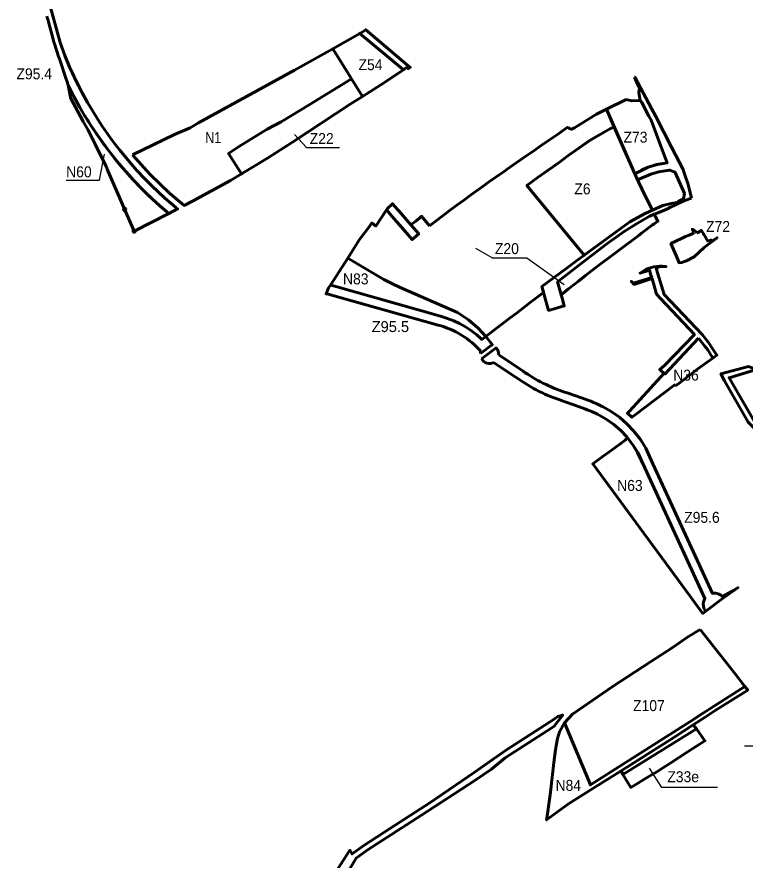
# Model space of a CAD drawing. Extents: x -650277 to -643420, y -1073980 to -1066720.
# Drawn here: x -649120 to -647523, y -1072548 to -1070698 of the extents above; entities that cross this region are included whole.
import ezdxf

# ---------------------------------------------------------------- set-up
doc = ezdxf.new("R2010")
doc.units = 0
doc.header["$LTSCALE"] = 9.6
doc.header["$PDMODE"] = 32
doc.header["$PDSIZE"] = 4.8
for name, color, linetype, lineweight in [('1', 7, 'Continuous', 60), ('15', 7, 'Continuous', 60), ('18', 7, 'Continuous', 60), ('34', 7, 'Continuous', 60), ('42', 7, 'Continuous', 60), ('45', 7, 'Continuous', 60), ('60', 7, 'Continuous', 60), ('63', 7, 'Continuous', 25), ('7', 7, 'Continuous', 60), ('8', 7, 'Continuous', 60), ('9', 7, 'Continuous', 60)]:
    doc.layers.add(name, color=color, linetype=linetype, lineweight=lineweight)

msp = doc.modelspace()

# ---------------------------------------------------------------- linework, layer by layer
at = {"layer": '1'}
for points in [[(-648540.7, -1070928.6), (-648571.14, -1070944.67), (-648634.07, -1070983.17), (-648655.76, -1070997.5), (-648627.39, -1071042.65), (-648605.3, -1071029.34), (-648570.23, -1071008.2), (-648515.46, -1070972.94), (-648389.33, -1070889.79), (-648362.519, -1070872.788), (-648386.587, -1070833.807), (-648479.18, -1070891.26)], [(-648215.08, -1071156.35), (-648232.8, -1071135.6), (-648237.46, -1071139.38), (-648245.49, -1071145.91), (-648256.04, -1071154.5), (-648238.84, -1071174.33), (-648253.126, -1071186.542), (-648292.587, -1071141.054), (-648309.41, -1071121.655), (-648333.002, -1071157.07), (-648341.943, -1071150.071), (-648347.949, -1071158.385), (-648368.48, -1071186.81), (-648394.104, -1071227.17), (-648315.127, -1071274.052), (-648292.406, -1071286.112), (-648274.918, -1071293.751), (-648154.21, -1071346.477), (-648130, -1071363), (-648109, -1071381), (-648091.92, -1071399.07), (-648060.01, -1071374.69), (-648038.18, -1071358.51), (-648025.39, -1071348.76), (-647994.31, -1071325.03), (-647965.26, -1071302.86), (-647966.226, -1071299.385), (-647968.896, -1071289.779), (-647916.208, -1071250.662), (-647895.959, -1071235.746), (-647875.939, -1071221.104), (-648001.922, -1071067.83), (-647977.41, -1071049.74), (-647930.96, -1071017.383), (-647912.11, -1071003.11), (-647864.29, -1070969.503), (-647818.33, -1070942.91), (-647810.243, -1070939.825), (-647827.527, -1070900.351), (-647848.89, -1070911.21), (-647897.76, -1070941.62), (-647904.13, -1070944.78), (-647909.42, -1070942.63), (-647908.63, -1070942.1), (-647913.45, -1070940.79), (-647934.9, -1070955.87), (-647952.01, -1070967.82), (-647970.19, -1070980.45), (-647988.81, -1070993.27), (-648008.34, -1071006.32), (-648030.24, -1071021.91), (-648044.82, -1071032.25), (-648051.48, -1071036.97), (-648062.53, -1071044.59), (-648085.73, -1071060.92), (-648097.61, -1071069.37), (-648102.55, -1071072.86), (-648125.53, -1071089.51), (-648141.12, -1071100.71), (-648155.77, -1071111.23), (-648172.48, -1071123.95), (-648197.57, -1071143.03)], [(-648001.922, -1071067.83), (-647977.41, -1071049.74), (-647930.7, -1071017.18), (-647911.838, -1071002.919), (-647864.03, -1070969.3), (-647864.03, -1070969.3), (-647818.33, -1070942.91), (-647810.243, -1070939.825), (-647759.52, -1071055.67), (-647757.19, -1071059.66), (-647742.64, -1071090.72), (-647726.74, -1071122.48), (-647742.35, -1071129.43), (-647775.982, -1071148.001), (-647775.982, -1071148.001), (-647875.939, -1071221.104)], [(-647756.03, -1071176.76), (-647750.34, -1071172.5), (-647726.56, -1071154.68), (-647723.79, -1071152.61), (-647720.85, -1071150.41), (-647714.71, -1071146.51), (-647719.73, -1071136.48), (-647722.51, -1071130.93), (-647732.58, -1071135.04), (-647733.38, -1071135.37), (-647737.027, -1071137.593), (-647761.366, -1071152.304), (-647788.66, -1071168.8), (-647826.56, -1071195.86), (-647889.22, -1071244.48), (-647915.6, -1071264.95), (-647934.6, -1071279.45), (-647926.69, -1071307.81), (-647910.73, -1071295.08), (-647907.92, -1071292.84), (-647888.77, -1071277.56), (-647873.25, -1071265.17), (-647850.956, -1071248.208)]]:
    msp.add_lwpolyline(points, close=True, dxfattribs=at)
at = {"layer": '15'}
msp.add_line((-648272.453, -1070814.072), (-648271.1, -1070813.17), dxfattribs=at)
for points in [[(-648271.1, -1070813.17), (-648267.8, -1070810.96), (-648264.38, -1070808.66), (-648262.15, -1070811.96), (-648257.61, -1070808.91), (-648355.275, -1070726.455), (-648360.83, -1070729.87), (-648366.739, -1070733.501), (-648368.163, -1070734.376), (-648272.453, -1070814.072)], [(-647659.01, -1071032.66), (-647685.1, -1070983.93), (-647719.06, -1070916.45), (-647728.35, -1070899.11), (-647764.84, -1070830.47), (-647765.72, -1070830.64)], [(-647765.72, -1070830.64), (-647759.08, -1070845.74), (-647755.87, -1070853.02), (-647754.6, -1070856.11), (-647756.45, -1070863.95), (-647753.81, -1070881.3)], [(-647753.81, -1070881.3), (-647749.75, -1070886.1), (-647734.48, -1070915.94), (-647729.27, -1070924.35), (-647701.45, -1070999.4)], [(-647701.45, -1070999.4), (-647694.54, -1071018.549), (-647718, -1071022), (-647736, -1071028), (-647750, -1071034), (-647765.408, -1071042.223), (-647759.52, -1071055.67), (-647730.17, -1071043.21), (-647712.74, -1071037.99), (-647688.9, -1071034.18), (-647676.96, -1071039.014)], [(-647640.727, -1071095.819), (-647648.106, -1071065.551), (-647654.747, -1071047.095), (-647657.699, -1071038.232), (-647659.01, -1071032.66)], [(-647676.96, -1071039.014), (-647676.9, -1071039.03), (-647676.45, -1071039.22), (-647656.443, -1071085.369), (-647658.55, -1071097.02), (-647669.02, -1071102.33), (-647667.35, -1071106.38), (-647655.47, -1071100.98), (-647640.727, -1071095.819)], [(-647498.271, -1071593.544), (-647558.654, -1071489.738), (-647498.8, -1071471.94), (-647515.87, -1071465.25), (-647576.471, -1071481.091), (-647568.35, -1071496.656), (-647516.376, -1071586.89), (-647490.561, -1071613.609)]]:
    msp.add_lwpolyline(points, dxfattribs=at)
for points in [[(-647734.48, -1070915.94), (-647741.21, -1070902.78), (-647749.75, -1070886.1)], [(-648238.84, -1071174.33), (-648256.04, -1071154.5), (-648278.39, -1071128.74), (-648296.34, -1071108.04), (-648307.33, -1071118.47), (-648309.41, -1071121.655), (-648292.587, -1071141.054), (-648270.236, -1071166.815), (-648253.126, -1071186.542)], [(-647826.56, -1071195.86), (-647788.66, -1071168.8), (-647761.366, -1071152.304), (-647737.027, -1071137.593), (-647733.38, -1071135.37), (-647732.58, -1071135.04), (-647722.51, -1071130.93), (-647716.51, -1071128.48), (-647695.08, -1071119.72), (-647685.55, -1071115.14), (-647684.15, -1071114.47), (-647680.64, -1071112.77), (-647667.35, -1071106.38), (-647669.02, -1071102.33), (-647674.17, -1071104.97), (-647675.64, -1071105.71), (-647680.82, -1071106.54), (-647688.45, -1071108.38), (-647701.04, -1071111.41), (-647703.96, -1071112.11), (-647726.74, -1071122.48), (-647742.35, -1071129.43), (-647775.982, -1071148.001), (-647895.959, -1071235.746), (-647916.161, -1071250.628), (-647916.208, -1071250.662), (-647968.896, -1071289.779), (-647965.26, -1071302.86), (-647954.38, -1071342), (-647934.51, -1071336.37), (-647919.88, -1071332.23), (-647924.53, -1071315.55), (-647934.6, -1071279.45), (-647915.6, -1071264.95), (-647889.22, -1071244.48)], [(-647625.428, -1071403.267), (-647612.269, -1071419.742), (-647605.292, -1071428.816), (-647594.43, -1071446.543), (-647585.273, -1071440.044), (-647595.335, -1071424.564), (-647603.9, -1071412.1), (-647617.49, -1071394.901), (-647700.816, -1071307.512), (-647715.355, -1071259.885), (-647718.342, -1071248.972), (-647711.447, -1071246.332), (-647696.81, -1071245.79), (-647705.59, -1071245.08), (-647710.94, -1071244.65), (-647723.57, -1071246.66), (-647738.56, -1071251.13), (-647753.647, -1071260.178), (-647733.15, -1071254.081), (-647729.795, -1071265.066), (-647728.006, -1071269.975), (-647768.445, -1071282.6), (-647772.97, -1071278.43), (-647772.07, -1071279.33), (-647766.35, -1071285.11), (-647727.368, -1071272.362), (-647717.363, -1071306.29), (-647708.429, -1071316.821), (-647634.524, -1071394.901), (-647700.078, -1071462.96), (-647710.546, -1071472.023), (-647699.767, -1071481.617)], [(-647795.4, -1072352.415), (-647679.66, -1072279.15), (-647637.082, -1072251.377), (-647629.67, -1072259.82), (-647791.198, -1072360.119)]]:
    msp.add_lwpolyline(points, close=True, dxfattribs=at)
at = {"layer": '18'}
for points in [[(-647783.95, -1070879.58), (-647827.363, -1070900.725), (-647765.408, -1071042.223), (-647736, -1071028), (-647715.488, -1071021.631)], [(-647783.95, -1070879.58), (-647827.363, -1070900.725), (-647765.408, -1071042.223), (-647736, -1071028), (-647715.488, -1071021.631)], [(-647715.488, -1071021.631), (-647694.54, -1071018.549), (-647701.45, -1070999.4), (-647729.27, -1070924.35), (-647734.48, -1070915.94), (-647749.75, -1070886.1), (-647753.81, -1070881.3), (-647771.47, -1070882.27), (-647783.95, -1070879.58)], [(-647715.488, -1071021.631), (-647694.54, -1071018.549), (-647701.45, -1070999.4), (-647729.27, -1070924.35), (-647734.48, -1070915.94), (-647749.75, -1070886.1), (-647753.81, -1070881.3), (-647771.47, -1070882.27), (-647783.95, -1070879.58)]]:
    msp.add_lwpolyline(points, dxfattribs=at)
at = {"layer": '34'}
for points in [[(-647621.97, -1072041.73), (-647649.76, -1072059.06), (-647683.63, -1072081.94), (-647730.53, -1072112.84), (-647814.58, -1072167.67), (-647845.58, -1072188.94), (-647901.91, -1072227.6), (-647919.68, -1072247.09), (-647862.615, -1072383.084)], [(-647523.71, -1072167.071), (-647545.44, -1072139.35), (-647621.97, -1072041.73)], [(-647862.615, -1072383.084), (-647800.2, -1072343.615), (-647642.504, -1072242.974), (-647616.719, -1072226.154), (-647523.71, -1072167.071)]]:
    msp.add_lwpolyline(points, dxfattribs=at)
at = {"layer": '42'}
for p, q in [((-648883.73, -1071120.13), (-648862.97, -1071168.09)), ((-648862.97, -1071168.09), (-648787.207, -1071129.363))]:
    msp.add_line(p, q, dxfattribs=at)
for points in [[(-649002.97, -1070857.609), (-649007.885, -1070848.153), (-649003.1, -1070871.35), (-649002.82, -1070872.69), (-649002.62, -1070873.69), (-649002.15, -1070875.96), (-648974.4, -1070927.77), (-648963.5, -1070946.45), (-648959.92, -1070953.73), (-648948.29, -1070977.37), (-648924.92, -1071024.89), (-648922.98, -1071029.49), (-648921.87, -1071032.04), (-648892.82, -1071099.15), (-648883.73, -1071120.13)], [(-648994.42, -1070874.053), (-648994.464, -1070873.974), (-648994.52, -1070873.867)], [(-648982.403, -1070895.812), (-648982.467, -1070895.704), (-648982.524, -1070895.601)], [(-648970.64, -1070915.778), (-648970.712, -1070915.663), (-648970.771, -1070915.564)], [(-648960.194, -1070932.542), (-648960.268, -1070932.429), (-648960.34, -1070932.313)], [(-648949.345, -1070949.096), (-648949.389, -1070949.031), (-648949.428, -1070948.972)], [(-648939.179, -1070963.89), (-648939.232, -1070963.818), (-648939.33, -1070963.675)], [(-648918.464, -1070992.141), (-648918.601, -1070991.969), (-648918.737, -1070991.784)], [(-648292.406, -1071286.112), (-648315.127, -1071274.052), (-648394.104, -1071227.17), (-648432.093, -1071286.645)], [(-648432.093, -1071286.645), (-648426.18, -1071288.32), (-648191.25, -1071354.858)], [(-648091.92, -1071399.07), (-648109, -1071381), (-648130, -1071363), (-648154.21, -1071346.477), (-648274.918, -1071293.751), (-648292.406, -1071286.112)], [(-648191.25, -1071354.858), (-648178.158, -1071358.781), (-648162.084, -1071364.918), (-648149.571, -1071370.788), (-648136.263, -1071378.194), (-648123.313, -1071386.696), (-648111.646, -1071395.618), (-648103.268, -1071402.88), (-648100.438, -1071405.517), (-648091.92, -1071399.07)], [(-647625.428, -1071403.267), (-647699.767, -1071481.617), (-647701.415, -1071480.15), (-647708.18, -1071487.57), (-647776.13, -1071562.1)], [(-647676.51, -1071504.34), (-647674.28, -1071506.59), (-647656.27, -1071493.04), (-647626.7, -1071470.46), (-647611.82, -1071459.38), (-647594.43, -1071446.543), (-647605.292, -1071428.816), (-647612.269, -1071419.742), (-647625.428, -1071403.267)], [(-647776.13, -1071562.1), (-647781.31, -1071567.79), (-647771.717, -1071576.551), (-647764.23, -1071571.01), (-647676.51, -1071504.34)], [(-647637.082, -1072251.377), (-647611.306, -1072234.563), (-647589.02, -1072219.66), (-647517.51, -1072174.98), (-647523.71, -1072167.071), (-647616.719, -1072226.154), (-647642.504, -1072242.974), (-647800.2, -1072343.615)], [(-647800.2, -1072343.615), (-647862.615, -1072383.084), (-647919.68, -1072247.09), (-647930.36, -1072266.38), (-647934.86, -1072280.99), (-647939.26, -1072306.1), (-647942.54, -1072333.82), (-647950.2, -1072398.61), (-647956.786, -1072446.511), (-647958.82, -1072459.74), (-647910.27, -1072424.51), (-647857.52, -1072391.14), (-647795.4, -1072352.415)], [(-647795.4, -1072352.415), (-647679.66, -1072279.15), (-647637.082, -1072251.377)]]:
    msp.add_lwpolyline(points, dxfattribs=at)
for start, end in [(206.85611, 208.07207), (208.08607, 209.71957), (209.73567, 211.25686), (211.27351, 212.56631), (212.58435, 213.8879), (213.89777, 215.07157), (215.08899, 217.38409), (217.41391, 230.04071)]:
    msp.add_arc((-648232.695, -1070467.567), 863.398, start, end, dxfattribs=at)
for p in [(-648883.73, -1071120.13), (-648862.97, -1071168.09)]:
    msp.add_point(p, dxfattribs=at)
at = {"layer": '45'}
msp.add_lwpolyline([(-647817.33, -1071649.51), (-647806.35, -1071641.47), (-647795.76, -1071633.72), (-647794.98, -1071633.15), (-647786.1, -1071626.65), (-647781.134, -1071621.645), (-647769.498, -1071636.647), (-647758.889, -1071653.742), (-647743.48, -1071687.426), (-647611.514, -1071974.086), (-647613.455, -1071978.031), (-647614.654, -1071982.238), (-647615.083, -1071986.65), (-647614.76, -1071990.762), (-647613.637, -1071995.081), (-647611.779, -1071999.069), (-647609.808, -1072001.962), (-647616.12, -1072006.7), (-647621.06, -1072000), (-647644.38, -1071968.3), (-647705.291, -1071885.501), (-647727.85, -1071854.86), (-647857.52, -1071678.92), (-647834.345, -1071661.969), (-647827.42, -1071656.89)], close=True, dxfattribs=at)
at = {"layer": '60'}
for points in [[(-649054.31, -1070696.44), (-649052.77, -1070702.25), (-649052.44, -1070703.48), (-649051.03, -1070708.74), (-649040.03, -1070750.06), (-649039.38, -1070752.51), (-649039.06, -1070753.72), (-649038.51, -1070755.38), (-649027.74, -1070787.51), (-649027.64, -1070787.8), (-649019.48, -1070812.18), (-649018.48, -1070815.18), (-649011.24, -1070836.79), (-649010.67, -1070838.5), (-649007.885, -1070848.153), (-648994.464, -1070873.974), (-648982.467, -1070895.704), (-648970.712, -1070915.663), (-648960.268, -1070932.429), (-648949.389, -1070949.031), (-648939.232, -1070963.818), (-648918.601, -1070991.969), (-648896.068, -1071020.184), (-648886.874, -1071031.044), (-648874.793, -1071044.773), (-648863.847, -1071056.723), (-648851.175, -1071069.886), (-648838.696, -1071082.562), (-648823.087, -1071097.562), (-648816.379, -1071103.782), (-648806.239, -1071112.938), (-648797, -1071121), (-648790.23, -1071126.818), (-648787.207, -1071129.363), (-648767.824, -1071119.455), (-648771.725, -1071116.233), (-648781.806, -1071107.721), (-648795.407, -1071095.8), (-648824.292, -1071068.677), (-648839.273, -1071053.556), (-648856.883, -1071034.761), (-648869.629, -1071020.411), (-648880.44, -1071007.703), (-648894.164, -1070990.806), (-648902.714, -1070979.812), (-648912.396, -1070966.893), (-648922.92, -1070952.242), (-648932.78, -1070937.887), (-648943.414, -1070921.659), (-648953.605, -1070905.299), (-648965.093, -1070885.794), (-648976.834, -1070864.527), (-648985.145, -1070848.538), (-648991.386, -1070835.954), (-648998.132, -1070821.723), (-649003.641, -1070809.566), (-649014.888, -1070782.994), (-649025.129, -1070754.377), (-649047.11, -1070674.743)], [(-648103.894, -1071436.836), (-648079.108, -1071418.564), (-648077.53, -1071417.4), (-648091.92, -1071399.07), (-648100.438, -1071405.517), (-648103.268, -1071402.88), (-648111.646, -1071395.618), (-648123.313, -1071386.696), (-648136.263, -1071378.194), (-648149.571, -1071370.788), (-648162.084, -1071364.918), (-648178.158, -1071358.781), (-648191.25, -1071354.858), (-648426.18, -1071288.32), (-648432.093, -1071286.645), (-648437.16, -1071292.53), (-648442.191, -1071305.453), (-648437.454, -1071306.778), (-648196.236, -1071374.226)], [(-648063.593, -1071439.723), (-648063.862, -1071435.078), (-648064.838, -1071431.28), (-648066.623, -1071427.592), (-648069.022, -1071424.443), (-648101.203, -1071448.31)], [(-647834.953, -1071553.406), (-647837.929, -1071551.872), (-647843.891, -1071549), (-647849.898, -1071546.282), (-647855.937, -1071543.707), (-647861.998, -1071541.254), (-647868.073, -1071538.911), (-647874.155, -1071536.658), (-647880.233, -1071534.48), (-647886.305, -1071532.36), (-647892.363, -1071530.282), (-647901.28, -1071527.249), (-647907.294, -1071525.204), (-647913.282, -1071523.152), (-647919.238, -1071521.081), (-647925.157, -1071518.976), (-647931.035, -1071516.824), (-647936.866, -1071514.613), (-647942.644, -1071512.329), (-647948.363, -1071509.96), (-647954.016, -1071507.496), (-647959.792, -1071504.833), (-647966.547, -1071501.883), (-647972.035, -1071499.009), (-647977.67, -1071495.885), (-647983.266, -1071492.628), (-647988.829, -1071489.259), (-647994.366, -1071485.79), (-647999.887, -1071482.241), (-648005.399, -1071478.627), (-648010.917, -1071474.963), (-648016.446, -1071471.268), (-648063.593, -1071439.723)], [(-648101.203, -1071448.31), (-648098.259, -1071452.196), (-648096.014, -1071454.192), (-648093.059, -1071456.066), (-648089.539, -1071457.489), (-648085.585, -1071458.248), (-648081.642, -1071458.215), (-648078.539, -1071457.636), (-648074.86, -1071456.248)], [(-648074.86, -1071456.248), (-648027.562, -1071487.894), (-648022.005, -1071491.607), (-648016.415, -1071495.321), (-648010.777, -1071499.017), (-648005.082, -1071502.678), (-647999.319, -1071506.287), (-647993.478, -1071509.826), (-647987.55, -1071513.275), (-647981.525, -1071516.615), (-647975.201, -1071519.929), (-647967.982, -1071523.081), (-647962.2, -1071525.746), (-647956.187, -1071528.368), (-647950.146, -1071530.869), (-647944.088, -1071533.263), (-647938.019, -1071535.566), (-647931.945, -1071537.788), (-647925.874, -1071539.949), (-647919.808, -1071542.058), (-647913.756, -1071544.132), (-647907.72, -1071546.185), (-647898.827, -1071549.208), (-647892.847, -1071551.26), (-647886.903, -1071553.336), (-647881.001, -1071555.45), (-647875.147, -1071557.619), (-647869.348, -1071559.856), (-647863.611, -1071562.177), (-647857.944, -1071564.594), (-647847.103, -1071569.497)], [(-647847.103, -1071569.497), (-647828.141, -1071580.34), (-647811.272, -1071592.28), (-647796.24, -1071605.324), (-647782.97, -1071619.278)], [(-647725.629, -1071678.373), (-647735.352, -1071657.117), (-647741.34, -1071644.028), (-647753.065, -1071625.201), (-647767.784, -1071606.225), (-647782.408, -1071590.847), (-647798.911, -1071576.526), (-647817.375, -1071563.458), (-647834.953, -1071553.406)], [(-647782.97, -1071619.278), (-647769.498, -1071636.647), (-647758.994, -1071653.513), (-647743.48, -1071687.426), (-647611.514, -1071974.086)], [(-647570.747, -1071972.644), (-647538.922, -1071950.099), (-647551.962, -1071958.049), (-647573.283, -1071969.627), (-647575.415, -1071967.709), (-647577.881, -1071965.979), (-647581.036, -1071964.346), (-647584.363, -1071963.196), (-647588.064, -1071962.51), (-647591.518, -1071962.387), (-647594.731, -1071962.714), (-647725.614, -1071678.405), (-647726.774, -1071675.885), (-647725.629, -1071678.373)], [(-647611.514, -1071974.086), (-647613.455, -1071978.031), (-647614.654, -1071982.238), (-647615.083, -1071986.65), (-647614.76, -1071990.762), (-647613.637, -1071995.081), (-647611.779, -1071999.069), (-647609.808, -1072001.962), (-647570.747, -1071972.644)], [(-648401.91, -1072586.1), (-648376.47, -1072543.52), (-648351.83, -1072525.81), (-648232.86, -1072449.45), (-648116.32, -1072373.44), (-648079.76, -1072348.46), (-648049.33, -1072323.77), (-647946.88, -1072257.82), (-647941.77, -1072254.45), (-647934.9, -1072244.55), (-647923.16, -1072229.85), (-647933.95, -1072233.18), (-647942.21, -1072238.54), (-648046.69, -1072306.3), (-648117.12, -1072356), (-648214.73, -1072422.41), (-648300.98, -1072478.1), (-648359.61, -1072515.85), (-648385.28, -1072534.41), (-648389.69, -1072526.36), (-648416.41, -1072567.43)]]:
    msp.add_lwpolyline(points, dxfattribs=at)
for centre, radius, start, end in [((-648244.965, -1071557.871), 190, 41.59858, 75.13936), ((-648083.781, -1071438.172), 20.157, 161.35794, 176.20098)]:
    msp.add_arc(centre, radius, start, end, dxfattribs=at)
at = {"layer": '63'}
for p, q in [((-648078, -1071227), (-648114, -1071206)), ((-647525, -1072297), (-647387, -1072297))]:
    msp.add_line(p, q, dxfattribs=at)
for points in [[(-648511, -1070956), (-648485, -1070985), (-648413, -1070985)], [(-649012, -1071056), (-648939, -1071056), (-648928, -1070999)], [(-648078, -1071227), (-648002, -1071227), (-647920, -1071285)], [(-648078, -1071227), (-648002, -1071227), (-647920, -1071285)], [(-647584, -1072389), (-647706, -1072389), (-647733, -1072346)]]:
    msp.add_lwpolyline(points, dxfattribs=at)
at = {"layer": '7'}
msp.add_lwpolyline([(-648866.341, -1071000.881), (-648828.353, -1071043.265), (-648785.386, -1071084.634), (-648758.423, -1071107.756), (-648752.967, -1071111.861), (-648734.849, -1071102.599), (-648651.375, -1071057.109), (-648627.39, -1071042.65), (-648655.76, -1070997.5), (-648634.07, -1070983.17), (-648571.14, -1070944.67), (-648540.7, -1070928.6), (-648479.18, -1070891.26), (-648386.587, -1070833.807), (-648396.611, -1070817.573), (-648407.667, -1070799.667), (-648427.25, -1070767.95), (-648511.09, -1070814.7), (-648721.54, -1070930.88), (-648740.25, -1070941.21), (-648774.23, -1070956.42)], close=True, dxfattribs=at)
at = {"layer": '8'}
msp.add_lwpolyline([(-647629.67, -1072259.82), (-647611.51, -1072286.26), (-647648.09, -1072309.95), (-647688.26, -1072336.06), (-647702.35, -1072345.14), (-647716.62, -1072353.95), (-647730.97, -1072362.6), (-647745.32, -1072371.26), (-647759.68, -1072379.91), (-647774.04, -1072388.57), (-647791.198, -1072360.119)], close=True, dxfattribs=at)
at = {"layer": '9'}
for points in [[(-648368.163, -1070734.376), (-648427.25, -1070767.95), (-648362.519, -1070872.788), (-648322.17, -1070847.2), (-648272.45, -1070814.075)], [(-647497.04, -1071595.66), (-647440.67, -1071558.93), (-647492.3, -1071470), (-647495.85, -1071471.06), (-647558.654, -1071489.738)]]:
    msp.add_lwpolyline(points, close=True, dxfattribs=at)
for points in [[(-647629.09, -1071172.4), (-647632.93, -1071167.71), (-647638.46, -1071163.89), (-647639.32, -1071164.22), (-647635.93, -1071171.22)], [(-647674.6, -1071221.71), (-647668.226, -1071237.571), (-647667.77, -1071237.5), (-647661.99, -1071236.62), (-647658.78, -1071235.63), (-647651.93, -1071233.57), (-647635.17, -1071224.18), (-647613.09, -1071204.33), (-647607.02, -1071199.34), (-647584.92, -1071182.54), (-647597.164, -1071189.857), (-647598.215, -1071187.608), (-647604.576, -1071190.781)], [(-647635.93, -1071171.22), (-647637.87, -1071173.29), (-647646.09, -1071176.68), (-647653.85, -1071179.87), (-647662.634, -1071183.968)], [(-647612.695, -1071177.542), (-647613.91, -1071175.57), (-647614.732, -1071174.222), (-647618.446, -1071168.166), (-647618.469, -1071168.129), (-647618.77, -1071167.64), (-647619.264, -1071166.832), (-647619.34, -1071166.709), (-647628.39, -1071172.05), (-647629.09, -1071172.4)], [(-647604.576, -1071190.781), (-647604.888, -1071190.272), (-647612.695, -1071177.542)], [(-647662.634, -1071183.968), (-647686.01, -1071195.35), (-647686.01, -1071195.35)], [(-647686.01, -1071195.35), (-647686.01, -1071195.35), (-647674.6, -1071221.71)]]:
    msp.add_lwpolyline(points, dxfattribs=at)

# ---------------------------------------------------------------- texts
at = {"layer": '63'}
for s, width, p in [('Z54', 0.95, (-648371, -1070815)), ('Z95.4', 0.95, (-649121, -1070835)), ('N1', 0.85, (-648707, -1070975)), ('Z22', 0.95, (-648478, -1070977)), ('Z73', 0.95, (-647790, -1070974)), ('N60', 0.95, (-649012, -1071050)), ('Z6', 0.95, (-647897.847, -1071087.452)), ('Z6', 0.95, (-647897.847, -1071087.452)), ('Z72', 0.95, (-647609, -1071170)), ('Z20', 0.95, (-648071.847, -1071218.452)), ('Z20', 0.95, (-648071.847, -1071218.452)), ('N83', 0.95, (-648405, -1071285)), ('N36', 0.95, (-647681, -1071496)), ('N63', 0.95, (-647804, -1071738)), ('Z95.6', 0.95, (-647657, -1071808)), ('Z107', 0.95, (-647769, -1072221)), ('Z33e', 0.95, (-647694, -1072377)), ('N84', 0.95, (-647939, -1072396))]:
    msp.add_text(s, height=24, dxfattribs=dict(at, width=width)).set_placement(p)
msp.add_text('Z95.5', height=24, dxfattribs=at).set_placement((-648342.123, -1071389.545))

doc.saveas('drawing.dxf')
